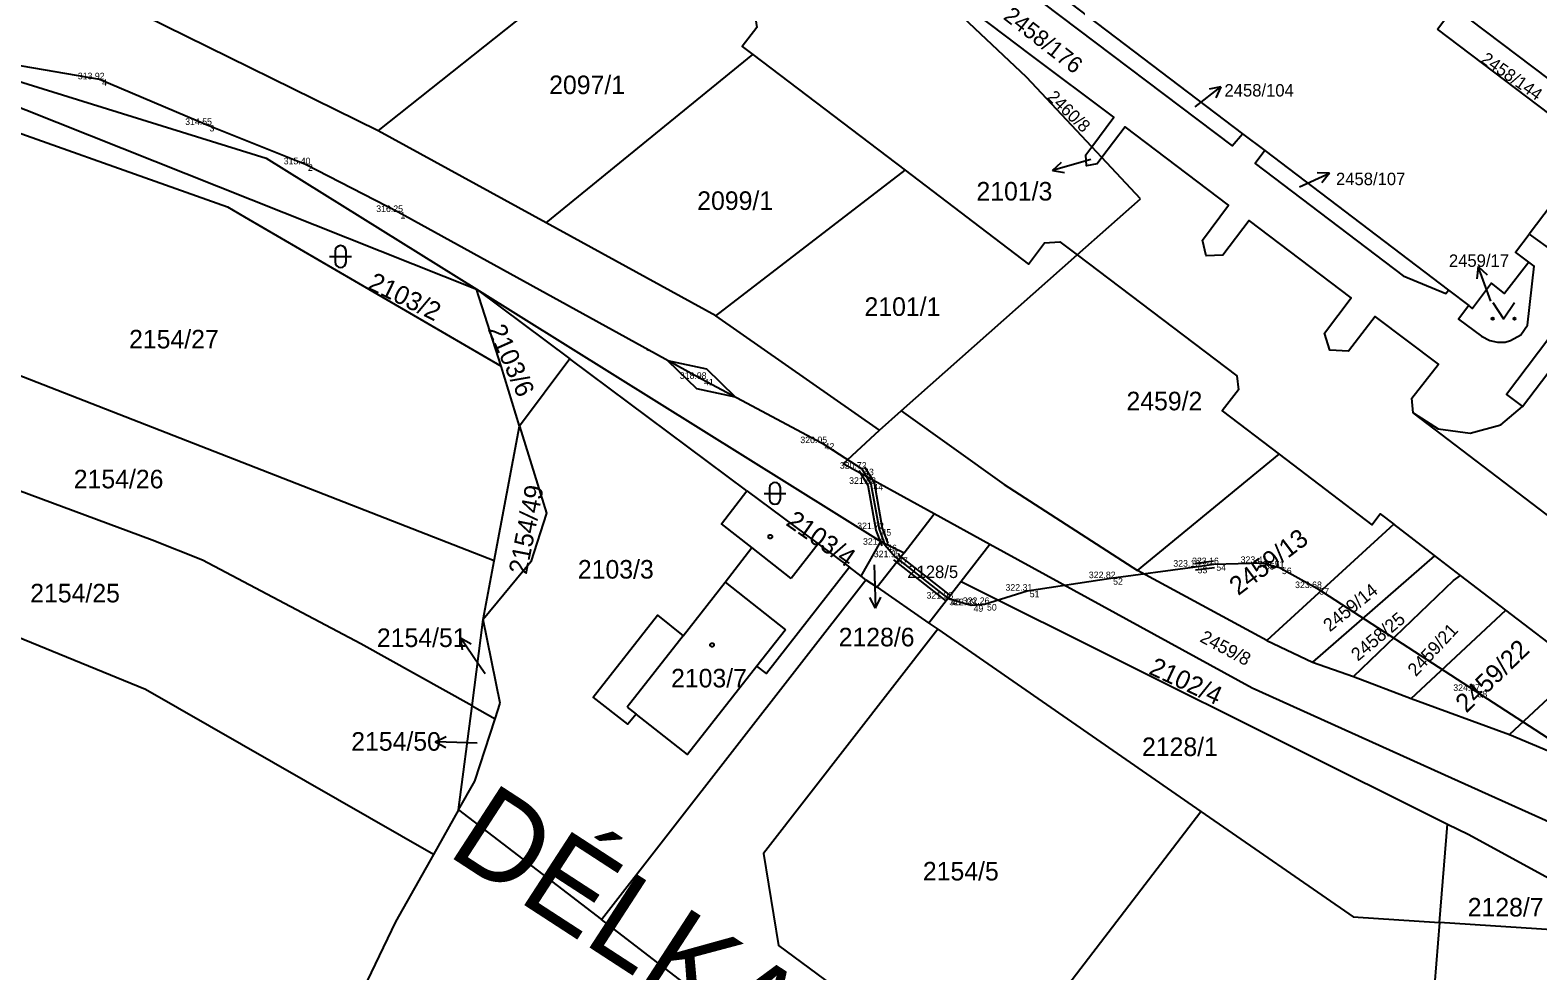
# Model space of a CAD drawing. Extents: x -606208 to -605570, y -1157873 to -1157573.
# Drawn here: x -606068.9 to -605930.7, y -1157739 to -1157652.8 of the extents above; entities that cross this region are included whole.
import ezdxf

# ---------------------------------------------------------------- set-up
doc = ezdxf.new("R2010")
doc.units = 0
for name, color, linetype in [('Vrstva 23', 7, 'Continuous'), ('Vrstva 30', 7, 'Continuous'), ('Vrstva 38', 7, 'Continuous'), ('Vrstva 58', 7, 'Continuous'), ('Vrstva 59', 7, 'Continuous'), ('Vrstva 60', 7, 'Continuous'), ('Vrstva 62', 7, 'Continuous')]:
    doc.layers.add(name, color=color, linetype=linetype)

msp = doc.modelspace()

# ---------------------------------------------------------------- linework, layer by layer
at = {"layer": 'Vrstva 23'}
for p, q in [((-606012.21, -1157682.16), (-606012.39, -1157682.07)), ((-606002.51, -1157687.34), (-606002.33, -1157687.43))]:
    msp.add_line(p, q, dxfattribs=at)
msp.add_lwpolyline([(-606010.45, -1157683.1), (-606007.83, -1157685.63), (-606004.27, -1157686.4), (-606006.89, -1157683.87)], close=True, dxfattribs=at)
at = {"layer": 'Vrstva 30'}
msp.add_lwpolyline([(-606074.86, -1157655.17), (-606062.53, -1157657.3), (-606052.69, -1157661.48), (-606043.66, -1157665.09), (-606035.18, -1157669.46), (-606007.36, -1157684.75), (-605996.31, -1157690.64), (-605992.69, -1157692.98), (-605991.84, -1157694.37), (-605991.1, -1157698.52), (-605990.57, -1157699.95), (-605989.58, -1157701.09), (-605984.75, -1157704.88), (-605982.66, -1157705.49), (-605981.43, -1157705.38), (-605977.51, -1157704.16), (-605969.87, -1157703.01), (-605962.13, -1157701.96), (-605960.41, -1157701.73), (-605955.96, -1157701.62), (-605954.4, -1157702.04), (-605950.97, -1157703.92), (-605936.47, -1157713.34), (-605923.26, -1157721.89)], dxfattribs=at)
at = {"layer": 'Vrstva 38'}
for p, q in [((-605989.77, -1157701.33), (-605984.94, -1157705.12)), ((-605989.39, -1157700.85), (-605984.56, -1157704.64)), ((-605962.17, -1157701.66), (-605960.45, -1157701.43)), ((-605962.09, -1157702.26), (-605960.37, -1157702.03))]:
    msp.add_line(p, q, dxfattribs=at)
for points in [[(-605992.95, -1157693.14), (-605992.13, -1157694.48), (-605991.39, -1157698.6), (-605990.85, -1157700.05)], [(-605992.43, -1157692.82), (-605991.55, -1157694.26), (-605990.81, -1157698.44), (-605990.29, -1157699.85)]]:
    msp.add_lwpolyline(points, dxfattribs=at)
at = {"layer": 'Vrstva 60'}
for p, q in [((-606062.53, -1157657.3), (-606062.53, -1157657.3)), ((-606052.69, -1157661.48), (-606052.69, -1157661.48)), ((-606043.66, -1157665.09), (-606043.66, -1157665.09)), ((-606035.18, -1157669.46), (-606035.18, -1157669.46)), ((-606007.36, -1157684.75), (-606007.36, -1157684.75)), ((-605996.31, -1157690.64), (-605996.31, -1157690.64)), ((-605992.69, -1157692.98), (-605992.69, -1157692.98)), ((-605991.84, -1157694.37), (-605991.84, -1157694.37)), ((-605991.1, -1157698.52), (-605991.1, -1157698.52)), ((-605990.57, -1157699.95), (-605990.57, -1157699.95)), ((-605989.58, -1157701.09), (-605989.58, -1157701.09)), ((-605962.13, -1157701.96), (-605962.13, -1157701.96)), ((-605960.41, -1157701.73), (-605960.41, -1157701.73)), ((-605955.96, -1157701.62), (-605955.96, -1157701.62)), ((-605969.87, -1157703.01), (-605969.87, -1157703.01)), ((-605954.4, -1157702.04), (-605954.4, -1157702.04)), ((-605977.51, -1157704.16), (-605977.51, -1157704.16)), ((-605950.97, -1157703.92), (-605950.97, -1157703.92)), ((-605984.75, -1157704.88), (-605984.75, -1157704.88)), ((-605982.66, -1157705.49), (-605982.66, -1157705.49)), ((-605981.43, -1157705.38), (-605981.43, -1157705.38)), ((-605936.47, -1157713.34), (-605936.47, -1157713.34))]:
    msp.add_line(p, q, dxfattribs=at)
at = {"layer": 'Vrstva 62'}
for p, q in [((-606037, -1157662.02), (-606013.04, -1157642.98)), ((-605975.11, -1157649.14), (-605957.79, -1157662.29)), ((-606037, -1157662.02), (-606058.47, -1157651.46)), ((-605925.55, -1157663.59), (-605939.92, -1157652.7)), ((-606021.61, -1157670.45), (-606002.66, -1157655.04)), ((-606002.66, -1157655.04), (-605988.71, -1157665.64)), ((-605962.12, -1157659.83), (-605959.76, -1157657.98)), ((-605959.76, -1157657.98), (-605960.85, -1157658.2)), ((-605959.76, -1157657.98), (-605960.24, -1157658.99)), ((-606021.61, -1157670.45), (-606037, -1157662.02)), ((-605957.79, -1157662.29), (-605955.75, -1157663.84)), ((-605971.7, -1157664.64), (-605972.32, -1157664.82)), ((-605970.68, -1157664.48), (-605971.61, -1157663.49)), ((-605970.68, -1157664.48), (-605971.61, -1157663.49)), ((-605967.14, -1157668.26), (-605970.68, -1157664.48)), ((-605967.14, -1157668.26), (-605970.68, -1157664.48)), ((-605955.75, -1157663.84), (-605938.91, -1157676.62)), ((-605925.55, -1157663.59), (-605931.53, -1157671.5)), ((-606006.06, -1157678.96), (-605988.71, -1157665.64)), ((-605972.32, -1157664.82), (-605975.2, -1157665.65)), ((-605975.2, -1157665.65), (-605974.38, -1157664.89)), ((-605975.2, -1157665.65), (-605974.1, -1157665.85)), ((-605952.55, -1157667.17), (-605949.83, -1157665.9)), ((-605949.83, -1157665.9), (-605950.95, -1157665.87)), ((-605949.83, -1157665.9), (-605950.53, -1157666.78)), ((-605972.93, -1157673.39), (-605967.14, -1157668.26)), ((-605972.93, -1157673.39), (-605967.14, -1157668.26)), ((-606006.06, -1157678.96), (-606021.61, -1157670.45)), ((-606041.45, -1157673.54), (-606039.45, -1157673.54)), ((-606040.95, -1157673.04), (-606040.95, -1157674.04)), ((-606039.95, -1157674.04), (-606039.95, -1157673.04)), ((-605989.08, -1157687.68), (-605972.93, -1157673.39)), ((-605989.08, -1157687.68), (-605972.93, -1157673.39)), ((-605936.18, -1157674.46), (-605936.3, -1157675.57)), ((-605935.15, -1157677.28), (-605936.18, -1157674.46)), ((-605936.18, -1157674.46), (-605935.36, -1157675.23)), ((-606025.74, -1157683.6), (-606027.99, -1157676.53)), ((-606027.99, -1157676.53), (-605990.92, -1157699.64)), ((-606027.99, -1157676.53), (-606019.44, -1157682.91)), ((-605938.91, -1157676.62), (-605937.05, -1157678.03)), ((-605935.02, -1157677.63), (-605935.15, -1157677.28)), ((-605991.06, -1157689.44), (-606006.06, -1157678.96)), ((-606026.37, -1157701.43), (-606079.93, -1157680.52)), ((-606024.05, -1157689.09), (-606025.74, -1157683.6)), ((-606019.44, -1157682.91), (-606024.05, -1157689.09)), ((-606003.21, -1157695.01), (-606019.44, -1157682.91)), ((-605991.06, -1157689.44), (-605989.08, -1157687.68)), ((-605991.06, -1157689.44), (-605989.08, -1157687.68)), ((-606026.37, -1157701.43), (-606024.05, -1157689.09)), ((-605994.39, -1157692.55), (-605991.06, -1157689.44)), ((-605994.39, -1157692.55), (-605991.06, -1157689.44)), ((-605967.4, -1157702.31), (-605954.44, -1157691.65)), ((-605986.04, -1157697.13), (-605994.39, -1157692.55)), ((-605986.04, -1157697.13), (-605994.39, -1157692.55)), ((-606001.14, -1157694.74), (-606001.14, -1157695.74)), ((-606000.14, -1157695.74), (-606000.14, -1157694.74)), ((-606001.64, -1157695.24), (-605999.64, -1157695.24)), ((-605988.81, -1157700.69), (-605986.04, -1157697.13)), ((-605980.93, -1157699.93), (-605986.04, -1157697.13)), ((-605980.93, -1157699.93), (-605986.04, -1157697.13)), ((-605943.93, -1157698.07), (-605955.57, -1157708.73)), ((-605940.18, -1157700.94), (-605943.93, -1157698.07)), ((-605999.15, -1157703.05), (-606002.77, -1157700.21)), ((-605996.68, -1157699.88), (-605999.15, -1157703.05)), ((-605992.74, -1157702.82), (-605990.92, -1157699.64)), ((-605990.92, -1157699.64), (-605988.81, -1157700.69)), ((-605980.93, -1157699.93), (-605983.56, -1157703.31)), ((-605956.91, -1157713.1), (-605980.93, -1157699.93)), ((-605956.91, -1157713.1), (-605980.93, -1157699.93)), ((-606027.38, -1157706.8), (-606026.37, -1157701.43)), ((-605991.54, -1157701.79), (-605991.51, -1157702.77)), ((-605988.81, -1157700.69), (-605991.26, -1157703.84)), ((-605937.81, -1157702.76), (-605940.18, -1157700.94)), ((-606016.54, -1157734.29), (-605992.3, -1157703.15)), ((-605992.74, -1157702.82), (-605993.82, -1157702.01)), ((-605992.3, -1157703.15), (-605992.74, -1157702.82)), ((-605992.3, -1157703.15), (-605991.26, -1157703.84)), ((-605991.51, -1157702.77), (-605991.41, -1157705.77)), ((-605983.56, -1157703.31), (-605986.53, -1157707.12)), ((-605983.56, -1157703.31), (-605938.99, -1157725.54)), ((-605955.57, -1157708.73), (-605967.4, -1157702.31)), ((-605933.66, -1157705.95), (-605937.81, -1157702.76)), ((-606005.2, -1157703.38), (-605999.67, -1157707.73)), ((-605991.41, -1157705.77), (-605990.94, -1157704.75)), ((-605991.26, -1157703.84), (-605986.53, -1157707.12)), ((-605991.41, -1157705.77), (-605991.94, -1157704.79)), ((-605942.33, -1157714.04), (-605933.66, -1157705.95)), ((-605926.77, -1157711.22), (-605933.66, -1157705.95)), ((-606028.4, -1157714.71), (-606027.38, -1157706.8)), ((-606025.83, -1157714.47), (-606027.38, -1157706.8)), ((-605986.53, -1157707.12), (-605985.7, -1157707.69)), ((-606027.77, -1157710.96), (-606029.45, -1157708.47)), ((-606029.45, -1157708.47), (-606028.47, -1157709.02)), ((-606029.45, -1157708.47), (-606029.3, -1157709.58)), ((-606009.04, -1157708.28), (-606014.18, -1157714.83)), ((-605999.67, -1157707.73), (-606002.29, -1157711.06)), ((-605985.7, -1157707.69), (-605961.6, -1157724.39)), ((-605955.57, -1157708.73), (-605951.38, -1157710.72)), ((-606028.4, -1157714.71), (-606038.6, -1157709.02)), ((-606027.21, -1157711.79), (-606027.77, -1157710.96)), ((-605951.38, -1157710.72), (-605947.61, -1157712.01)), ((-605926.77, -1157711.22), (-605933.32, -1157717.34)), ((-605947.61, -1157712.01), (-605942.33, -1157714.04)), ((-605938.64, -1157721.34), (-605956.91, -1157713.1)), ((-605938.64, -1157721.34), (-605956.91, -1157713.1)), ((-605942.33, -1157714.04), (-605933.32, -1157717.34)), ((-606029.63, -1157724.24), (-606028.4, -1157714.71)), ((-606028.4, -1157714.71), (-606026.29, -1157715.89)), ((-606026.29, -1157715.89), (-606025.83, -1157714.47)), ((-606014.18, -1157714.83), (-606013.37, -1157715.46)), ((-606028.14, -1157721.61), (-606026.29, -1157715.89)), ((-606031.79, -1157718), (-606030.77, -1157717.53)), ((-606028.79, -1157718.1), (-606031.79, -1157718)), ((-606031.79, -1157718), (-606030.81, -1157718.53)), ((-606027.94, -1157718.13), (-606028.79, -1157718.1)), ((-605933.32, -1157717.34), (-605920.23, -1157722.87)), ((-605919.8, -1157729.83), (-605938.64, -1157721.34)), ((-605919.8, -1157729.83), (-605938.64, -1157721.34)), ((-606029.63, -1157724.24), (-606028.14, -1157721.61)), ((-606029.63, -1157724.24), (-606031.93, -1157728.32)), ((-606029.63, -1157724.24), (-606016.54, -1157734.29)), ((-605981.87, -1157750.81), (-605961.6, -1157724.39)), ((-605961.6, -1157724.39), (-605947.66, -1157734.05)), ((-605939.73, -1157734.56), (-605938.99, -1157725.54)), ((-606003.76, -1157744.1), (-606016.54, -1157734.29)), ((-605947.66, -1157734.05), (-605939.73, -1157734.56)), ((-605939.73, -1157734.56), (-605941.6, -1157757.14)), ((-605919.91, -1157735.84), (-605939.73, -1157734.56))]:
    msp.add_line(p, q, dxfattribs=at)
for points in [[(-606013.04, -1157642.98), (-606003.58, -1157650.18), (-606002.55, -1157650.96), (-606002.31, -1157652.57), (-606003.64, -1157654.29), (-606002.66, -1157655.04)], [(-605899.2, -1157643.74), (-605900.85, -1157644.58), (-605901.7, -1157643.98), (-605933.59, -1157686.19), (-605932.13, -1157687.27)], [(-605932.13, -1157687.27), (-605900.17, -1157645.24), (-605899.2, -1157643.74)], [(-605971.61, -1157663.49), (-605969.59, -1157660.76), (-605977.24, -1157655.02), (-605986.78, -1157647.79), (-605987.07, -1157648.16)], [(-605971.61, -1157663.49), (-605977.59, -1157657.1), (-605987.07, -1157648.16)], [(-605971.61, -1157663.49), (-605977.59, -1157657.1), (-605987.07, -1157648.16)], [(-605975.11, -1157649.14), (-605976.05, -1157650.34), (-605958.73, -1157663.41), (-605957.79, -1157662.29)], [(-605939.92, -1157652.7), (-605938.41, -1157650.71), (-605923.95, -1157661.67)], [(-606168.75, -1157663.12), (-606157.1, -1157658.79), (-606121.27, -1157652.9), (-606097.17, -1157654.39), (-606075.51, -1157655.76), (-606047.27, -1157664.52), (-606027.99, -1157676.53)], [(-605931.53, -1157671.5), (-605929.23, -1157673.15), (-605929.66, -1157677.39), (-605913.15, -1157655.66)], [(-606076.85, -1157659.75), (-606072.33, -1157658.9), (-606027.99, -1157676.53)], [(-606076.85, -1157659.75), (-606050.81, -1157669), (-606049.26, -1157669.9), (-606025.74, -1157683.6)], [(-605942.14, -1157687.85), (-605942.28, -1157686.53), (-605939.84, -1157683.41), (-605945.62, -1157679.03), (-605948.07, -1157682.2), (-605949.77, -1157682.13), (-605950.27, -1157680.55), (-605947.83, -1157677.33), (-605957.19, -1157670.23), (-605959.6, -1157673.43), (-605961.13, -1157673.49), (-605961.46, -1157672.04), (-605959.07, -1157668.82), (-605968.53, -1157661.65), (-605970.68, -1157664.48)], [(-605970.68, -1157664.48), (-605971.1, -1157665.04), (-605972.08, -1157665.24), (-605972.16, -1157664.23), (-605971.61, -1157663.49)], [(-605955.75, -1157663.84), (-605956.62, -1157665.01), (-605943.06, -1157675.31), (-605939.14, -1157676.92), (-605938.91, -1157676.62)], [(-605988.71, -1157665.64), (-605977.4, -1157674.23), (-605975.94, -1157672.3), (-605974.52, -1157672.18), (-605972.93, -1157673.39)], [(-605931.55, -1157674.06), (-605932.77, -1157673.13), (-605931.53, -1157671.5)], [(-605972.93, -1157673.39), (-605958.31, -1157684.48), (-605958.16, -1157685.76), (-605959.64, -1157687.68), (-605954.44, -1157691.65)], [(-605937.05, -1157678.03), (-605937.98, -1157679.27), (-605935.9, -1157680.83), (-605935.11, -1157681.24), (-605934.42, -1157681.4), (-605933.73, -1157681.38), (-605933.22, -1157681.22), (-605932.28, -1157680.72), (-605931.68, -1157679.83), (-605931.05, -1157674.43), (-605931.55, -1157674.06)], [(-605931.55, -1157674.06), (-605933.78, -1157676.93), (-605934.97, -1157675.99), (-605936.71, -1157678.29), (-605937.05, -1157678.03)], [(-605934.86, -1157677.74), (-605933.86, -1157679.24), (-605932.86, -1157677.74)], [(-606038.6, -1157709.02), (-606053.11, -1157701.37), (-606057.71, -1157699.53), (-606085.4, -1157689.27), (-606095.61, -1157686.17)], [(-605989.08, -1157687.68), (-605979.64, -1157694.43), (-605967.4, -1157702.31)], [(-605942.14, -1157687.85), (-605939.87, -1157689.32), (-605936.93, -1157689.72), (-605934.11, -1157688.96), (-605932.13, -1157687.27)], [(-605927.39, -1157699.1), (-605929.95, -1157697.15), (-605942.14, -1157687.85)], [(-606024.05, -1157689.09), (-606021.59, -1157697.05), (-606023.01, -1157701.5), (-606027.38, -1157706.8)], [(-605954.44, -1157691.65), (-605945.94, -1157698.12), (-605945.16, -1157697.13), (-605943.93, -1157698.07)], [(-605993.82, -1157702.01), (-606001.42, -1157711.74), (-606002.29, -1157711.06), (-606008.65, -1157719.17), (-606013.37, -1157715.46), (-606014.12, -1157716.39), (-606017.29, -1157713.9), (-606011.4, -1157706.41), (-606009.04, -1157708.28), (-606005.2, -1157703.38), (-606002.77, -1157700.21), (-606005.55, -1157698.03), (-606003.21, -1157695.01)], [(-606003.21, -1157695.01), (-605996.68, -1157699.88), (-605993.82, -1157702.01)], [(-606031.93, -1157728.32), (-606058.33, -1157713.22), (-606076.06, -1157705.96), (-606101.34, -1157695.55)], [(-605940.18, -1157700.94), (-605940.19, -1157700.95), (-605951.38, -1157710.72)], [(-605947.61, -1157712.01), (-605938.44, -1157703.22), (-605937.81, -1157702.76)], [(-605985.7, -1157707.69), (-606001.7, -1157728.24), (-606000.3, -1157736.67), (-605992.45, -1157742.47), (-605981.87, -1157750.81)], [(-605938.99, -1157725.54), (-605937.1, -1157726.48), (-605919.91, -1157735.84)], [(-606031.93, -1157728.32), (-606035.41, -1157734.5), (-606044.76, -1157753.96)]]:
    msp.add_lwpolyline(points, dxfattribs=at)
for centre, radius in [((-605934.86, -1157679.24), 0.1), ((-605932.86, -1157679.24), 0.1), ((-606001.07, -1157699.21), 0.175), ((-606006.4, -1157709.13), 0.175)]:
    msp.add_circle(centre, radius, dxfattribs=at)
for centre, start, end in [((-606040.45, -1157673.04), 0, 180), ((-606040.45, -1157674.04), 180, 359.9879), ((-606000.64, -1157694.74), 0, 180), ((-606000.64, -1157695.74), 180, 359.9879)]:
    msp.add_arc(centre, 0.5, start, end, dxfattribs=at)

# ---------------------------------------------------------------- texts
at = {"layer": 'Vrstva 30'}
msp.add_text('DÉLKA OPTOTRASY 710m', height=8, rotation=326.99, dxfattribs=at).set_placement((-606030.83, -1157728.28))
at = {"layer": 'Vrstva 58'}
for s, p in [('313.92 ', (-606064.53, -1157657.3)), ('314.55 ', (-606054.69, -1157661.48)), ('315.40 ', (-606045.66, -1157665.09)), ('316.25 ', (-606037.18, -1157669.46)), ('318.98 ', (-606009.36, -1157684.75)), ('320.05 ', (-605998.31, -1157690.64)), ('320.72 ', (-605994.69, -1157692.98)), ('321.08 ', (-605993.84, -1157694.37)), ('321.72 ', (-605993.1, -1157698.52)), ('321.81 ', (-605992.57, -1157699.95)), ('321.95 ', (-605991.58, -1157701.09)), ('323.10 ', (-605964.13, -1157701.96)), ('323.16 ', (-605962.41, -1157701.73)), ('323.41 ', (-605957.96, -1157701.62)), ('323.51 ', (-605956.4, -1157702.04)), ('322.82 ', (-605971.87, -1157703.01)), ('323.68 ', (-605952.97, -1157703.92)), ('321.98 ', (-605986.75, -1157704.88)), ('322.31 ', (-605979.51, -1157704.16)), ('322.09 ', (-605984.66, -1157705.49)), ('322.26 ', (-605983.43, -1157705.38)), ('324.37 ', (-605938.47, -1157713.34))]:
    msp.add_text(s, height=0.6, dxfattribs=at).set_placement(p)
at = {"layer": 'Vrstva 59'}
for s, p in [(' 4', (-606062.53, -1157657.9)), (' 3', (-606052.69, -1157662.08)), (' 2', (-606043.66, -1157665.69)), (' 1', (-606035.18, -1157670.06)), (' 41', (-606007.36, -1157685.35)), (' 42', (-605996.31, -1157691.24)), (' 43', (-605992.69, -1157693.58)), (' 44', (-605991.84, -1157694.97)), (' 45', (-605991.1, -1157699.12)), (' 46', (-605990.57, -1157700.55)), (' 47', (-605989.58, -1157701.69)), (' 53', (-605962.13, -1157702.56)), (' 54', (-605960.41, -1157702.33)), (' 55', (-605955.96, -1157702.22)), (' 52', (-605969.87, -1157703.61)), (' 56', (-605954.4, -1157702.64)), (' 51', (-605977.51, -1157704.76)), (' 57', (-605950.97, -1157704.52)), (' 48', (-605984.75, -1157705.48)), (' 49', (-605982.66, -1157706.09)), (' 50', (-605981.43, -1157705.98)), (' 58', (-605936.47, -1157713.94))]:
    msp.add_text(s, height=0.6, dxfattribs=at).set_placement(p)
at = {"layer": 'Vrstva 62'}
for s, height, rotation, p in [('2458/176', 1.5, 322, (-605979.79, -1157651.72)), ('2458/144', 1.139, 325, (-605936.03, -1157655.67)), ('2460/8', 1.139, 316, (-605975.76, -1157659.02)), ('2103/2', 1.7, 334, (-606038.05, -1157676.45)), ('2103/6', 1.7, 294, (-606026.99, -1157680.21)), ('2154/49', 1.7, 79, (-606023.39, -1157702.74)), ('2103/4', 1.7, 325, (-605999.73, -1157698.09)), ('2459/13', 1.7, 37, (-605958.18, -1157704.66)), ('2459/14', 1.2, 39, (-605949.78, -1157707.98)), ('2458/25', 1.2, 40, (-605947.21, -1157710.67)), ('2459/21', 1.2, 47, (-605941.9, -1157712.09)), ('2459/8', 1.2, 332, (-605961.78, -1157708.78)), ('2459/22', 1.7, 44, (-605937.27, -1157715.42)), ('2102/4', 1.7, 335, (-605966.47, -1157711.74))]:
    msp.add_text(s, height=height, rotation=rotation, dxfattribs=at).set_placement(p)
for s, height, p in [('2097/1', 1.7, (-606021.33, -1157658.66)), ('2458/104', 1.139, (-605959.44, -1157658.88)), ('2458/107', 1.139, (-605949.22, -1157667)), ('2101/3', 1.7, (-605982.17, -1157668.41)), ('2099/1', 1.7, (-606007.76, -1157669.27)), ('2459/17', 1.139, (-605938.87, -1157674.49)), ('2101/1', 1.7, (-605992.43, -1157678.98)), ('2154/27', 1.7, (-606059.83, -1157681.96)), ('2459/2', 1.7, (-605968.42, -1157687.63)), ('2154/26', 1.7, (-606064.9, -1157694.78)), ('2103/3', 1.7, (-606018.7, -1157703.05)), ('2128/5', 1.14, (-605988.51, -1157703)), ('2154/25', 1.7, (-606068.89, -1157705.23)), ('2128/6', 1.7, (-605994.8, -1157709.26)), ('2154/51', 1.7, (-606037.12, -1157709.32)), ('2103/7', 1.7, (-606010.16, -1157713.02)), ('2154/50', 1.7, (-606039.47, -1157718.82)), ('2128/1', 1.7, (-605967, -1157719.31)), ('2154/5', 1.7, (-605987.08, -1157730.71)), ('2128/7', 1.7, (-605937.15, -1157734.01))]:
    msp.add_text(s, height=height, dxfattribs=at).set_placement(p)

doc.saveas('drawing.dxf')
